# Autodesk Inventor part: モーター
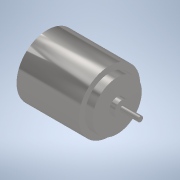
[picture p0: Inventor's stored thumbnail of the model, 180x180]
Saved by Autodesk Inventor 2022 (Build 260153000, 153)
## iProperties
Created: 2024-10
Part Number: モーター
Material: 鋼、鋳鋼
Document SubType Name: Modeling
Designer: jsat7
Density: 7.85 g/cm^3
Appearance: 半つや出し
Author: jsat7
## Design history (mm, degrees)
sketch "スケッチ1"
  geometry: 1 further point
sketch "スケッチ2"
  geometry: L1 (0, 0)-(27, 0); L2 (27, 0)-(27, 3); L3 (27, 3)-(25, 3); L4 (25, 3)-(25, 9.5); L5 (25, 9.5)-(22, 9.5); L6 (22, 9.5)-(22, 11.85); L7 (22, 11.85)-(0, 11.85); L8 (0, 11.85)-(0, 0)
  constraints: 16 end point, 7 perpendicular, 1 horizontal
  dimensions: "d0" = 22 distance of L6.end L7.end; "d1" = 25 distance from line of L8 L4.end; "d2" = 3 distance between parallel lines of L1 L3; "d3" = 9.5 distance from line of L1 L4.end; "d4" = 11.85 distance between parallel lines of L1 L7; "d5" = 2 distance of L2.end L3.end
revolve "回転1" sketch "スケッチ2" stored, may be unused: angle "d6" = 90 deg
sketch "スケッチ3"
  geometry: L1 (0, 0)-(-4, 0); L2 (-4, 0)-(-4, 4.25); L3 (-4, 4.25)-(-2, 4.25); L4 (-2, 4.25)-(-2, 11.85); L5 (0, -11.85)-(0, 11.85) reference; L6 (-2, 11.85)-(0, 11.85); L7 (0, 11.85)-(0, 0)
  constraints: 12 end point, 5 perpendicular, 1 horizontal
  dimensions: "d7" = 2 distance of L2.end L3.end; "d8" = 2 distance of L4.end L5.end; "d9" = 4.25 distance of L1.end L2.end
revolve "回転2" sketch "スケッチ3" stored, may be unused: angle "d10" = 90 deg
sketch "スケッチ4"
  geometry: C1 r 1 at (0, 0); 1 further point
  constraints: 1 centre point, 1 coincident
  dimensions: "d11" = 2 diameter of C1
extrude "押し出し1" join sketch "スケッチ4" distance "d12" = 7; taper "d13" = 0 deg
sketch "スケッチ5"
  geometry: C1 r 1 at (0, 0) reference; C2 r 1 at (0, 0); 1 further point
  constraints: 1 centre point, 1 coincident
  dimensions: "d14" = 2 diameter of C2
extrude "押し出し2" join sketch "スケッチ5" distance "d15" = 1; taper "d16" = 0 deg
sketch "スケッチ6"
  geometry: 1 further point
node "作業平面1"
node "ソリッド1"
node "ソリッド2"
other parameters: "d17" = 9.25
